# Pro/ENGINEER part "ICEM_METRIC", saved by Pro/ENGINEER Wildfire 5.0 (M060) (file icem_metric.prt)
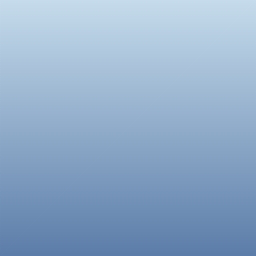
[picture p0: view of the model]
Units: hd_metric; MM, KILOGRAM, SECS
Materials in the file: DEFAULT

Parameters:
  DRW_UNITS = "METRIC"
  TOL_NAME = "MILLIMETERS"
  SUR = "6.3"
  LINEAR_TOL_0 = "1.0"
  PTC_COMMON_NAME = "icem.prt"
  PTC_MATERIAL_NAME = "DEFAULT"

Other named items: CS_DEF, PT_ORIG, ICEM_IN, SIDE, TOP, FRONT

Layers: ANNOT, AXES, COSMETIC, CS, CURVES, DATUMS, DEF_CS, DEF_DATUMS, GEOM_CRVS, GEOM_DATUMS, GEOM_PNTS, ICEM_ARCHIVE, PTS, SURFS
